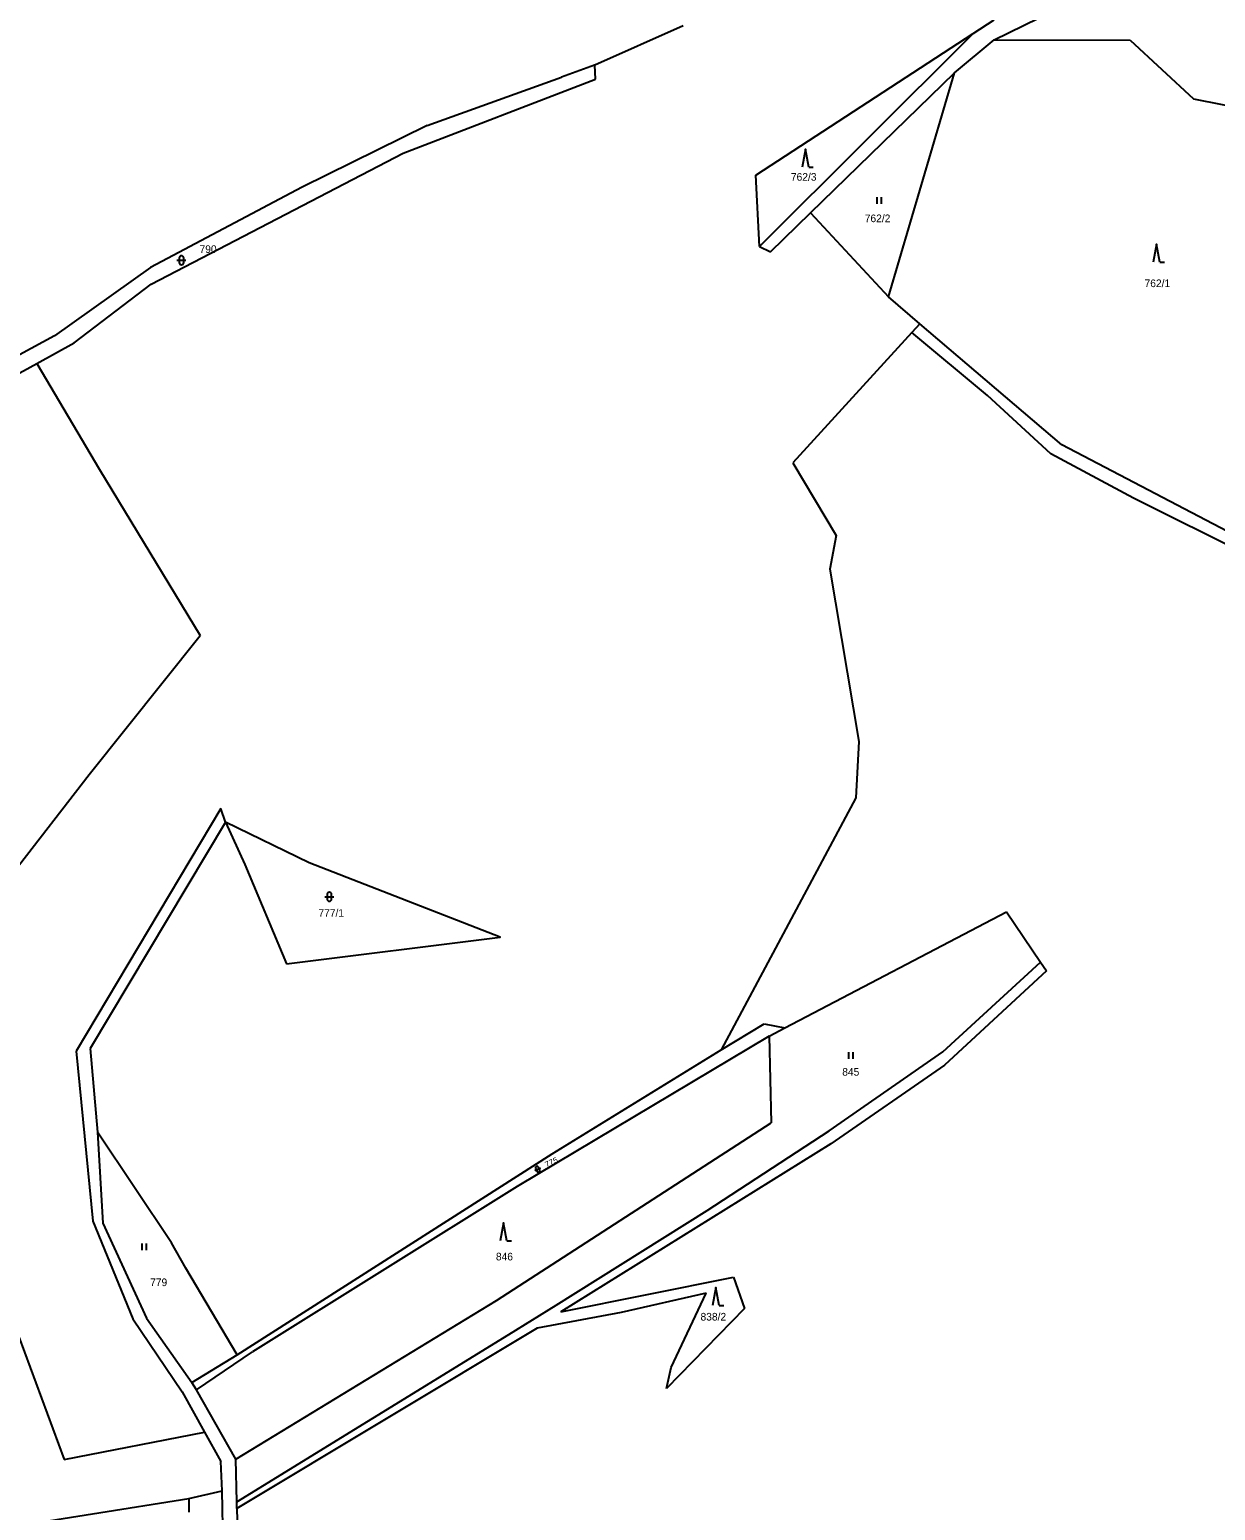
# Model space of a CAD drawing. Extents: x -744132 to -742433, y -984679 to -982287.
# Drawn here: x -743900.1 to -743636.5, y -983014.5 to -982685.5 of the extents above; entities that cross this region are included whole.
import ezdxf

# ---------------------------------------------------------------- set-up
doc = ezdxf.new("R2010")
doc.units = 0
doc.header["$LTSCALE"] = 0.68
doc.layers.add('1', color=7, linetype='Continuous', lineweight=25)
doc.layers.add('3', color=7, linetype='Continuous', lineweight=25)
doc.layers.add('2', color=7, linetype='Continuous')

msp = doc.modelspace()

# ---------------------------------------------------------------- linework, layer by layer
at = {"layer": '1'}
for p, q in [((-743685.73, -982687.7), (-743641.11, -982665.94)), ((-743754.84, -982684.62), (-743774.47, -982693.38)), ((-743738.69, -982717.8), (-743690.33, -982686.31)), ((-743690.33, -982686.31), (-743737.87, -982733.66)), ((-743690.33, -982686.31), (-743685.67, -982683.3)), ((-743694.53, -982695.1), (-743685.73, -982687.7)), ((-743685.73, -982687.7), (-743655.48, -982687.79)), ((-743655.48, -982687.79), (-743641.35, -982700.84)), ((-743811.78, -982706.74), (-743781.9, -982696)), ((-743774.57, -982693.36), (-743781.9, -982696)), ((-743774.47, -982693.38), (-743774.57, -982693.36)), ((-743774.34, -982696.48), (-743774.47, -982693.38)), ((-743726.52, -982726.15), (-743694.53, -982695.1)), ((-743709.2, -982744.85), (-743694.53, -982695.1)), ((-743817.11, -982712.92), (-743774.34, -982696.48)), ((-743641.35, -982700.84), (-743610.26, -982707.04)), ((-743811.78, -982706.74), (-743839.55, -982720.49)), ((-743873.14, -982742.04), (-743817.11, -982712.92)), ((-743737.87, -982733.66), (-743738.69, -982717.8)), ((-743839.55, -982720.49), (-743873.23, -982738.3)), ((-743735.44, -982734.81), (-743726.52, -982726.15)), ((-743726.52, -982726.15), (-743709.2, -982744.85)), ((-743737.87, -982733.66), (-743735.44, -982734.81)), ((-743873.23, -982738.3), (-743894.57, -982753.52)), ((-743890.21, -982755.1), (-743873.14, -982742.04)), ((-743702.22, -982750.86), (-743709.2, -982744.85)), ((-743894.57, -982753.52), (-743923.29, -982768.96)), ((-743898.51, -982759.63), (-743890.21, -982755.1)), ((-743703.99, -982752.77), (-743730.45, -982781.72)), ((-743687.21, -982766.77), (-743703.99, -982752.77)), ((-743921.67, -982772.27), (-743898.51, -982759.63)), ((-743898.51, -982759.63), (-743884.6, -982783.22)), ((-743673.09, -982779.74), (-743687.21, -982766.77)), ((-743582.04, -982824.08), (-743670.68, -982777.75)), ((-743730.45, -982781.72), (-743720.81, -982797.89)), ((-743654.75, -982789.61), (-743673.09, -982779.74)), ((-743884.6, -982783.22), (-743862.19, -982820.11)), ((-743609.33, -982812.2), (-743654.75, -982789.61)), ((-743720.81, -982797.89), (-743722.22, -982805.39)), ((-743722.22, -982805.39), (-743715.75, -982843.62)), ((-743886.85, -982851.02), (-743862.19, -982820.11)), ((-743715.75, -982843.62), (-743716.48, -982856.15)), ((-743903.83, -982872.89), (-743886.85, -982851.02)), ((-743716.48, -982856.15), (-743746.38, -982912.17)), ((-743857.61, -982858.57), (-743889.74, -982912.5)), ((-743856.55, -982861.6), (-743857.61, -982858.57)), ((-743856.55, -982861.6), (-743886.64, -982911.88)), ((-743837.97, -982870.62), (-743856.55, -982861.6)), ((-743856.55, -982861.6), (-743852.29, -982871)), ((-743852.29, -982871), (-743843.05, -982893.05)), ((-743732.26, -982907.31), (-743682.96, -982881.48)), ((-743682.96, -982881.48), (-743675.36, -982892.7)), ((-743697.09, -982912.61), (-743675.36, -982892.7)), ((-743675.36, -982892.7), (-743674.08, -982894.64)), ((-743674.08, -982894.64), (-743696.72, -982915.58)), ((-743746.38, -982912.17), (-743736.82, -982906.39)), ((-743736.82, -982906.39), (-743732.26, -982907.31)), ((-743735.7, -982909.11), (-743791.73, -982942.55)), ((-743735.7, -982909.11), (-743732.26, -982907.31)), ((-743735.7, -982909.11), (-743735.3, -982928.37)), ((-743889.74, -982912.5), (-743886.09, -982950.23)), ((-743886.64, -982911.88), (-743885.07, -982930.5)), ((-743783.96, -982935.27), (-743746.38, -982912.17)), ((-743722.4, -982930.16), (-743697.09, -982912.61)), ((-743925.38, -982914.22), (-743892.48, -983003.17)), ((-743696.72, -982915.58), (-743722, -982933.09)), ((-743796.33, -982967.85), (-743735.3, -982928.37)), ((-743885.07, -982930.5), (-743883.84, -982950.65)), ((-743868.57, -982955.05), (-743885.07, -982930.5)), ((-743722, -982933.09), (-743782.03, -982970.41)), ((-743749.47, -982947.88), (-743722.4, -982930.16)), ((-743853.97, -982979.94), (-743783.96, -982935.27)), ((-743791.73, -982942.55), (-743850.56, -982979.25)), ((-743783.08, -982968.88), (-743749.47, -982947.88)), ((-743886.09, -982950.23), (-743877.2, -982971.98)), ((-743883.84, -982950.65), (-743874.14, -982971.79)), ((-743865.43, -982960.68), (-743868.57, -982955.05)), ((-743853.97, -982979.94), (-743865.43, -982960.68)), ((-743782.03, -982970.41), (-743743.62, -982962.66)), ((-743743.62, -982962.66), (-743741.18, -982969.67)), ((-743854.25, -983003.12), (-743796.33, -982967.85)), ((-743793.56, -982975.45), (-743783.08, -982968.88)), ((-743749.72, -982966.27), (-743768.58, -982970.52)), ((-743757.47, -982982.79), (-743749.72, -982966.27)), ((-743877.2, -982971.98), (-743866.2, -982988.18)), ((-743874.14, -982971.79), (-743864.03, -982986.12)), ((-743768.58, -982970.52), (-743787.27, -982974.05)), ((-743741.18, -982969.67), (-743758.57, -982987.44)), ((-743854.06, -983012.62), (-743793.56, -982975.45)), ((-743787.27, -982974.05), (-743854.03, -983014.11)), ((-743864.03, -982986.12), (-743853.97, -982979.94)), ((-743863.02, -982987.74), (-743850.56, -982979.25)), ((-743758.57, -982987.44), (-743757.47, -982982.79)), ((-743866.2, -982988.18), (-743861.24, -982997.13)), ((-743863.02, -982987.74), (-743864.03, -982986.12)), ((-743854.25, -983003.12), (-743863.02, -982987.74)), ((-743892.48, -983003.17), (-743861.24, -982997.13)), ((-743861.24, -982997.13), (-743857.64, -983003.62)), ((-743857.33, -983010.2), (-743857.64, -983003.62)), ((-743946.2, -983024.79), (-743864.76, -983011.89)), ((-743864.76, -983011.89), (-743857.33, -983010.2)), ((-743864.76, -983011.89), (-743864.74, -983014.91)), ((-743856.71, -983041.1), (-743857.33, -983010.2)), ((-743854.03, -983014.11), (-743853.38, -983042.28))]:
    msp.add_line(p, q, dxfattribs=at)
for points in [[(-743670.68, -982777.75), (-743702.22, -982750.86), (-743703.99, -982752.77)], [(-743843.05, -982893.05), (-743795.51, -982887.14), (-743837.97, -982870.62)], [(-743854.03, -983014.11), (-743854.06, -983012.62), (-743854.25, -983003.12)]]:
    msp.add_lwpolyline(points, dxfattribs=at)
at = {"layer": '3'}
for p, q in [((-743726.9, -982716.01), (-743725.904, -982716.01)), ((-743711.711, -982724.18), (-743711.711, -982722.68)), ((-743710.71, -982724.18), (-743710.71, -982722.68)), ((-743867.371, -982736.711), (-743865.369, -982736.711)), ((-743866.871, -982736.211), (-743866.871, -982737.212)), ((-743865.869, -982737.212), (-743865.869, -982736.211)), ((-743648.83, -982737.15), (-743647.834, -982737.15)), ((-743834.491, -982878.141), (-743832.489, -982878.141)), ((-743833.991, -982877.641), (-743833.991, -982878.642)), ((-743832.989, -982878.642), (-743832.989, -982877.641)), ((-743718.031, -982914.2), (-743718.031, -982912.7)), ((-743717.03, -982914.2), (-743717.03, -982912.7)), ((-743787.796, -982938.999), (-743786.537, -982938.384)), ((-743787.635, -982938.53), (-743787.328, -982939.16)), ((-743786.698, -982938.853), (-743787.005, -982938.223)), ((-743875.141, -982956.67), (-743875.141, -982955.17)), ((-743874.14, -982956.67), (-743874.14, -982955.17)), ((-743794, -982954.64), (-743793.004, -982954.64)), ((-743746.8, -982969.01), (-743745.804, -982969.01))]:
    msp.add_line(p, q, dxfattribs=at)
for points in [[(-743726.9, -982716.01), (-743727.65, -982712.01), (-743728.4, -982716.01)], [(-743648.83, -982737.15), (-743649.58, -982733.15), (-743650.33, -982737.15)], [(-743794, -982954.64), (-743794.75, -982950.64), (-743795.5, -982954.64)], [(-743746.8, -982969.01), (-743747.55, -982965.01), (-743748.3, -982969.01)]]:
    msp.add_lwpolyline(points, dxfattribs=at)
for centre, radius, start, end in [((-743866.37, -982736.2109), 0.5, 0, 180), ((-743866.37, -982737.2109), 0.5, 180, 359.98789), ((-743833.49, -982877.6409), 0.5, 0, 180), ((-743833.49, -982878.6409), 0.5, 180, 359.98789), ((-743787.32, -982938.3768), 0.35, 26, 206), ((-743787.0132, -982939.006), 0.35, 206, 25.98789)]:
    msp.add_arc(centre, radius, start, end, dxfattribs=at)

# ---------------------------------------------------------------- texts
at = {"layer": '2'}
for s, p in [('762/3', (-743730.88, -982719.045)), ('762/2', (-743714.46, -982728.255)), ('790', (-743862.35, -982735.095)), ('762/1', (-743652.26, -982742.685)), ('777/1', (-743835.92, -982882.615)), ('845', (-743719.47, -982917.915)), ('846', (-743796.46, -982958.965)), ('779', (-743873.33, -982964.675)), ('838/2', (-743750.97, -982972.325))]:
    msp.add_text(s, height=1.7, dxfattribs=at).set_placement(p)
at = {"layer": '2', "width": 1.1}
msp.add_text('775', height=1.19, rotation=25, dxfattribs=at).set_placement((-743785.204, -982938.259))

doc.saveas('drawing.dxf')
